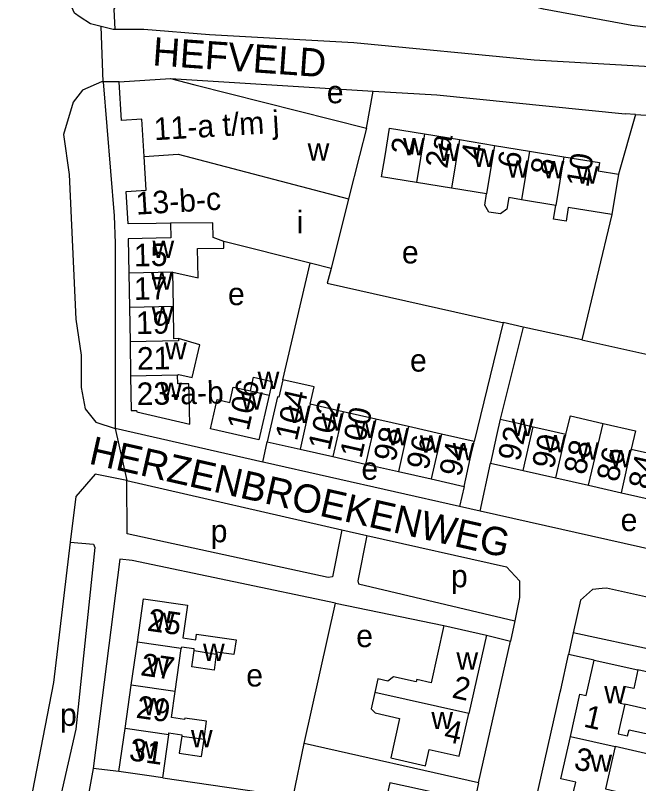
# Model space of a CAD drawing. Extents: x 163012 to 165277, y 382513 to 383987.
# Drawn here: x 163848.8 to 163959.5, y 383566.9 to 383703.3 of the extents above; entities that cross this region are included whole.
import ezdxf

# ---------------------------------------------------------------- set-up
doc = ezdxf.new("R2010")
doc.units = 0
for name, color, linetype in [('BLT_Basislijn', 7, 'Continuous'), ('BLT_Bebouwing', 7, 'Continuous'), ('BLT_Centroide', 7, 'Continuous'), ('BLT_Huisnummer', 7, 'Continuous'), ('BLT_Huisnummer_ tussenligend', 7, 'Continuous'), ('BLT_Huisnummer_reeks', 7, 'Continuous'), ('BLT_Onderverdeling_panden', 7, 'Continuous'), ('BLT_Straatnaam', 7, 'Continuous'), ('BLT_Vlakafsluiter', 7, 'Continuous')]:
    doc.layers.add(name, color=color, linetype=linetype)

msp = doc.modelspace()

# ---------------------------------------------------------------- linework, layer by layer
at = {"layer": 'BLT_Basislijn'}
for p, q in [((163864.34, 383691.46), (163864.06, 383691.46)), ((163867.17, 383691.48), (163864.34, 383691.46)), ((163876.3, 383692.03), (163912.31, 383689.83)), ((163911.11, 383683.25), (163912.31, 383689.83)), ((163958.91, 383685.64), (163955.89, 383675.07)), ((163958.91, 383685.64), (163957.06, 383685.77)), ((163958.91, 383685.64), (164004.75, 383682.98)), ((163954.72, 383667.91), (163949.39, 383645.66)), ((163896.25, 383638.61), (163901.09, 383659.27)), ((163935.4, 383648.75), (163930.26, 383627.64)), ((163938.97, 383647.95), (163934.89, 383631.6)), ((163938.97, 383647.95), (163935.4, 383648.75)), ((163949.39, 383645.66), (163938.97, 383647.95)), ((163949.39, 383645.66), (163990.87, 383636.39)), ((163892.68, 383624), (163866.5, 383629.96)), ((163892.68, 383624), (163893.49, 383627.6)), ((163931.33, 383615.29), (163933.13, 383623.81)), ((163868.54, 383620.71), (163906.76, 383611.96)), ((163928.46, 383619.68), (163927.66, 383616.12)), ((163931.33, 383615.29), (163927.66, 383616.12)), ((163983.4, 383603.59), (163931.33, 383615.29)), ((163906.76, 383611.96), (163911.21, 383610.95)), ((163900.04, 383574.07), (163905.62, 383598.92)), ((163905.62, 383598.92), (163924.87, 383594.99)), ((163937.48, 383595.84), (163936.71, 383592.2)), ((163932.43, 383593.29), (163936.71, 383592.2)), ((163947.84, 383593.68), (163946.99, 383589.85)), ((163975.18, 383587.76), (163947.84, 383593.68)), ((163931.03, 383567.07), (163936.71, 383592.2)), ((163945.61, 383583.59), (163946.99, 383589.85)), ((163951.54, 383588.86), (163946.99, 383589.85)), ((163976.48, 383583.2), (163959.34, 383587.1)), ((163976.54, 383576.59), (163956.98, 383581)), ((163898.07, 383564.6), (163900.04, 383574.07)), ((163931.03, 383567.07), (163900.04, 383574.07)), ((163867.16, 383569.05), (163862.59, 383569.6)), ((163874.93, 383567.94), (163898.07, 383564.6)), ((163931.03, 383567.07), (163907.55, 383460.42))]:
    msp.add_line(p, q, dxfattribs=at)
for points in [[(164049.11, 383697.12), (164020.26, 383697.6), (163986.78, 383698.92), (163970.65, 383700), (163958.23, 383701.46), (163942.55, 383704.38), (163930.77, 383707.49), (163916.3, 383712.29), (163898.28, 383719.17), (163879.5, 383726.81), (163866.23, 383704.35), (163866.45, 383700.78)], [(163860.29, 383702.92), (163859.23, 383703.63), (163858.28, 383705.77), (163857.55, 383709.28)], [(163864.02, 383701.27), (163862.08, 383701.73), (163860.29, 383702.92)], [(163866.45, 383700.78), (163866.12, 383700.78), (163864.02, 383701.27)], [(163964.63, 383693.94), (163940.93, 383695.32), (163908.87, 383698.4), (163883.22, 383699.83), (163871.58, 383700.78), (163866.45, 383700.78)], [(163864.06, 383691.46), (163860.66, 383689.97), (163859, 383687.84), (163857.33, 383682.14), (163858.28, 383675.01), (163859.47, 383649.36), (163860.42, 383642.95), (163860.42, 383637.25), (163861.13, 383633.45), (163863.03, 383631.08), (163866.5, 383629.96)], [(163864.34, 383691.46), (163866.32, 383667.71), (163866.46, 383662.83), (163866.5, 383629.96)], [(163912.31, 383689.83), (163923.59, 383689.14), (163957.06, 383685.77)], [(163904.83, 383658.33), (163904.14, 383655.71), (163935.01, 383648.84), (163935.4, 383648.75)], [(163927.66, 383616.12), (163892.98, 383623.93), (163892.68, 383624)], [(163868.54, 383620.71), (163862.9, 383621.83), (163859.49, 383617.87), (163858.48, 383609.78)], [(163906.76, 383611.96), (163905.06, 383603.63), (163904.34, 383603.52), (163868.64, 383611.23), (163868.54, 383620.71)], [(163911.21, 383610.95), (163909.57, 383602.93), (163909.73, 383602.38), (163937.48, 383595.84)], [(163911.21, 383610.95), (163936.01, 383605.38), (163938.31, 383602.89), (163938.27, 383599.94), (163937.48, 383595.84)], [(163858.48, 383609.78), (163862.64, 383609.43), (163862.86, 383608.82), (163859.49, 383576.6), (163853.78, 383551.38), (163852.82, 383551.19), (163849.14, 383551.93)], [(163858.48, 383609.78), (163855.5, 383584.89), (163849.14, 383551.93)], [(163905.62, 383598.92), (163869.51, 383606.52), (163867.33, 383606.74), (163862.59, 383569.6)], [(163977.2, 383596.4), (163953.73, 383601.62), (163952.97, 383601.58), (163951.27, 383601.38), (163949.15, 383599.47), (163947.84, 383593.68)], [(163941.12, 383563.72), (163945.51, 383583.15), (163945.61, 383583.59)], [(163862.59, 383569.6), (163859.01, 383550.05), (163841.02, 383473.95)]]:
    msp.add_lwpolyline(points, dxfattribs=at)
at = {"layer": 'BLT_Bebouwing'}
for p, q in [((163867.17, 383691.48), (163876.3, 383692.03)), ((163921.44, 383682.23), (163927.65, 383681.21)), ((163927.65, 383681.21), (163933.86, 383680.19)), ((163933.86, 383680.19), (163940.08, 383679.18)), ((163940.08, 383679.18), (163946.17, 383678.18)), ((163955.89, 383675.07), (163954.72, 383667.91)), ((163926.24, 383672.57), (163920.02, 383673.59)), ((163932.45, 383671.56), (163926.24, 383672.57)), ((163944.76, 383669.54), (163938.66, 383670.54)), ((163904.83, 383658.33), (163901.09, 383659.27)), ((163868.89, 383657.52), (163869, 383651.43)), ((163876.82, 383651.57), (163876.71, 383657.67)), ((163869, 383651.43), (163869.12, 383645.33)), ((163869.12, 383645.33), (163869.23, 383639.24)), ((163906.95, 383632.92), (163901.12, 383634.24)), ((163912.78, 383631.6), (163906.95, 383632.92)), ((163918.6, 383630.28), (163912.78, 383631.6)), ((163924.43, 383628.96), (163918.6, 383630.28)), ((163930.26, 383627.64), (163924.43, 383628.96)), ((163893.49, 383627.6), (163899.32, 383626.28)), ((163899.32, 383626.28), (163905.15, 383624.96)), ((163905.15, 383624.96), (163910.97, 383623.64)), ((163910.97, 383623.64), (163916.8, 383622.32)), ((163933.13, 383623.81), (163938.95, 383622.49)), ((163916.8, 383622.32), (163922.63, 383621)), ((163938.95, 383622.49), (163944.76, 383621.18)), ((163922.63, 383621), (163928.46, 383619.68)), ((163944.76, 383621.18), (163950.58, 383619.86)), ((163950.58, 383619.86), (163956.39, 383618.55)), ((163956.39, 383618.55), (163962.21, 383617.23)), ((163924.87, 383594.99), (163932.43, 383593.29)), ((163932.43, 383593.29), (163929.3, 383579.34)), ((163869.35, 383584.38), (163870.44, 383592.04)), ((163877.12, 383583.27), (163878.21, 383590.93)), ((163868.25, 383576.72), (163869.35, 383584.38)), ((163947.35, 383575.29), (163949.04, 383582.79)), ((163867.16, 383569.05), (163868.25, 383576.72)), ((163874.93, 383567.94), (163876.02, 383575.61))]:
    msp.add_line(p, q, dxfattribs=at)
for points in [[(163871.63, 383678.24), (163871.24, 383684.82), (163867.58, 383684.6), (163867.17, 383691.48)], [(163876.3, 383692.03), (163880.64, 383690.93), (163911.11, 383683.25)], [(163911.11, 383683.25), (163909.89, 383678.4), (163907.95, 383670.73)], [(163920.02, 383673.59), (163913.81, 383674.61), (163914.42, 383678.31), (163915.23, 383683.24), (163921.44, 383682.23)], [(163876.3, 383666.36), (163873.78, 383666.33), (163868.78, 383666.29), (163868.44, 383672.03), (163871.99, 383672.25), (163871.63, 383678.24)], [(163946.17, 383678.18), (163952.5, 383677.14), (163952.26, 383675.66), (163955.89, 383675.07)], [(163938.66, 383670.54), (163936.4, 383670.91), (163936.06, 383668.84), (163934.91, 383668.01), (163932.84, 383668.35), (163932.13, 383669.58), (163932.45, 383671.56)], [(163907.95, 383670.73), (163904.83, 383658.33)], [(163954.72, 383667.91), (163946.96, 383669.18), (163946.57, 383666.75), (163944.36, 383667.11), (163944.76, 383669.54)], [(163876.3, 383666.36), (163876.35, 383663.76), (163873.78, 383663.71), (163868.78, 383663.62), (163868.89, 383657.52)], [(163876.71, 383657.67), (163881.21, 383656.68), (163881.11, 383661.88), (163885.78, 383661.97), (163885.76, 383663.14)], [(163901.09, 383659.27), (163885.76, 383663.14)], [(163877.71, 383645.89), (163876.92, 383645.87), (163876.82, 383651.57)], [(163877.57, 383639.39), (163877.78, 383639.54), (163880.13, 383638.99), (163881.49, 383644.82), (163877.71, 383645.89)], [(163869.23, 383639.24), (163869.34, 383633.14), (163870.29, 383633.16), (163870.3, 383632.91), (163879.72, 383630.69), (163879.63, 383635.69), (163879.59, 383637.89), (163877.6, 383637.85), (163877.57, 383639.39)], [(163890.5, 383636.6), (163891.05, 383639.05), (163894.37, 383638.3), (163893.81, 383635.85)], [(163896.25, 383638.61), (163895.54, 383635.5), (163895.32, 383635.55), (163894.59, 383632.48), (163893.49, 383627.6)], [(163901.12, 383634.24), (163901.83, 383637.34), (163896.25, 383638.61)], [(163893.81, 383635.85), (163892.02, 383627.94), (163883.41, 383629.89), (163884.6, 383635.07), (163886.83, 383634.56), (163887.44, 383637.3), (163890.5, 383636.6)], [(163934.89, 383631.6), (163934.23, 383628.69), (163933.13, 383623.81)], [(163934.89, 383631.6), (163938.6, 383630.76), (163940.7, 383630.26)], [(163946.52, 383628.94), (163947.36, 383632.17), (163953.13, 383630.86)], [(163940.7, 383630.26), (163943.14, 383629.7), (163946.52, 383628.94)], [(163953.13, 383630.86), (163958.9, 383629.56), (163958.15, 383626.3)], [(163928.46, 383619.68), (163929.56, 383624.56), (163930.26, 383627.64)], [(163958.15, 383626.3), (163961.05, 383625.62), (163963.96, 383624.96)], [(163870.44, 383592.04), (163871.54, 383599.71), (163879.31, 383598.6), (163878.49, 383592.77), (163880.79, 383592.44), (163880.93, 383593.45), (163887.96, 383592.44), (163887.58, 383589.82), (163884.5, 383590.26), (163884.44, 383589.87)], [(163924.87, 383594.99), (163922.59, 383584.84), (163920.06, 383585.41), (163919.96, 383584.99), (163915.93, 383585.9), (163914.93, 383585.11), (163913.15, 383585.51), (163912.61, 383583.09)], [(163880.49, 383590.52), (163880.53, 383590.82), (163878.24, 383591.15), (163878.21, 383590.93)], [(163884.44, 383589.87), (163884.04, 383587.07), (163880.07, 383587.64), (163880.49, 383590.52)], [(163949.04, 383582.79), (163950.11, 383582.55), (163951.54, 383588.86)], [(163951.54, 383588.86), (163959.34, 383587.1)], [(163959.34, 383587.1), (163958.59, 383583.79), (163956.84, 383584.18), (163956.16, 383581.19), (163956.98, 383581)], [(163882.26, 383574.81), (163882.71, 383578.01), (163878.84, 383578.57), (163878.8, 383578.3), (163876.46, 383578.67), (163877.12, 383583.27)], [(163912.61, 383583.09), (163911.95, 383580.17), (163912.64, 383579.46), (163917, 383578.48), (163915.43, 383571.5), (163921.61, 383570.11), (163922.26, 383573.01), (163927.61, 383571.81), (163929.3, 383579.34)], [(163956.98, 383581), (163955.88, 383576.13), (163955.8, 383575.79), (163957.5, 383575.41), (163957.75, 383576.5), (163963.74, 383575.15), (163962.97, 383571.76), (163955.28, 383573.5)], [(163876.02, 383575.61), (163876.02, 383575.91), (163878.33, 383575.57), (163878.3, 383575.37)], [(163878.3, 383575.37), (163877.87, 383572.31), (163881.82, 383571.75), (163882.26, 383574.81)], [(163955.28, 383573.5), (163953.59, 383565.99), (163956.14, 383565.42), (163955.48, 383562.49), (163947.62, 383564.27), (163948.29, 383567.19), (163945.65, 383567.79), (163947.35, 383575.29)], [(163874.93, 383567.94), (163872.11, 383568.35), (163867.16, 383569.05)], [(163921.45, 383557.78), (163923.15, 383565.33), (163918.27, 383566.43), (163915.29, 383567.09), (163913.57, 383559.55)]]:
    msp.add_lwpolyline(points, dxfattribs=at)
at = {"layer": 'BLT_Onderverdeling_panden'}
for p, q in [((163921.44, 383682.23), (163920.02, 383673.59)), ((163927.65, 383681.21), (163926.24, 383672.57)), ((163933.86, 383680.19), (163932.45, 383671.56)), ((163940.08, 383679.18), (163938.66, 383670.54)), ((163946.17, 383678.18), (163944.76, 383669.54)), ((163876.71, 383657.67), (163868.89, 383657.52)), ((163876.82, 383651.57), (163869, 383651.43)), ((163877.57, 383639.39), (163869.23, 383639.24)), ((163890.5, 383636.6), (163893.81, 383635.85)), ((163901.12, 383634.24), (163899.32, 383626.28)), ((163906.95, 383632.92), (163905.15, 383624.96)), ((163912.78, 383631.6), (163910.97, 383623.64)), ((163918.6, 383630.28), (163916.8, 383622.32)), ((163938.95, 383622.49), (163940.7, 383630.26)), ((163950.58, 383619.86), (163953.13, 383630.86)), ((163924.43, 383628.96), (163922.63, 383621)), ((163944.76, 383621.18), (163946.52, 383628.94)), ((163956.39, 383618.55), (163958.15, 383626.3)), ((163878.21, 383590.93), (163870.44, 383592.04)), ((163880.49, 383590.52), (163884.44, 383589.87)), ((163877.12, 383583.27), (163869.35, 383584.38)), ((163929.3, 383579.34), (163912.61, 383583.09)), ((163876.02, 383575.61), (163868.25, 383576.72)), ((163878.3, 383575.37), (163882.26, 383574.81)), ((163947.35, 383575.29), (163955.28, 383573.5))]:
    msp.add_line(p, q, dxfattribs=at)
for points in [[(163871.63, 383678.24), (163877.68, 383678.6), (163907.95, 383670.73)], [(163885.76, 383663.14), (163883.86, 383663.83), (163883.84, 383666.42), (163876.3, 383666.36)], [(163877.71, 383645.89), (163877.72, 383645.49), (163869.12, 383645.33)]]:
    msp.add_lwpolyline(points, dxfattribs=at)
at = {"layer": 'BLT_Vlakafsluiter'}
for p, q in [((163864.34, 383691.46), (163864.02, 383701.27)), ((163866.5, 383629.96), (163868.54, 383620.71))]:
    msp.add_line(p, q, dxfattribs=at)

# ---------------------------------------------------------------- texts
at = {"layer": 'BLT_Centroide'}
for s, p in [('e', (163904.07, 383687.66)), ('w', (163900.66, 383677.49)), ('w', (163917.62, 383678.41)), ('w', (163923.84, 383677.41)), ('w', (163930.05, 383676.38)), ('w', (163936.09, 383674.45)), ('w', (163942.42, 383674.36)), ('w', (163948.44, 383673.38)), ('i', (163898.73, 383664.58)), ('w', (163873.1, 383660.22)), ('e', (163917.41, 383659.24)), ('w', (163872.85, 383654.56)), ('e', (163886.52, 383651.84)), ('w', (163872.97, 383648.47)), ('w', (163875.34, 383642.19)), ('e', (163918.85, 383640.04)), ('w', (163891.78, 383636.93)), ('w', (163874.48, 383635.03)), ('w', (163888.83, 383633.31)), ('w', (163897.31, 383630.92)), ('w', (163903.14, 383629.59)), ('w', (163908.97, 383628.28)), ('w', (163936.92, 383628.59)), ('w', (163914.78, 383626.97)), ('w', (163920.61, 383625.64)), ('w', (163942.73, 383625.7)), ('w', (163926.44, 383624.31)), ('w', (163948.55, 383624.39)), ('w', (163954.36, 383623.08)), ('e', (163910.22, 383620.85)), ('e', (163956.26, 383611.73)), ('p', (163883.45, 383609.76)), ('p', (163926.12, 383601.77)), ('w', (163873.17, 383594.18)), ('e', (163909.29, 383591.15)), ('w', (163882.08, 383588.7)), ('w', (163872.21, 383586.19)), ('w', (163927.09, 383587.16)), ('e', (163889.76, 383584.16)), ('w', (163953.34, 383581.2)), ('w', (163871.43, 383579.06)), ('p', (163856.69, 383577.17)), ('w', (163922.63, 383576.59)), ('w', (163879.93, 383573.39)), ('w', (163869.92, 383571.38)), ('w', (163950.89, 383569.02))]:
    msp.add_text(s, height=4, dxfattribs=at).set_placement(p)
at = {"layer": 'BLT_Huisnummer'}
for s, rotation, p in [('2a', 80.7013, (163925.46, 383675.96)), ('2', 80.7023, (163919.34, 383678.29)), ('4', 80.7023, (163931.81, 383677.3)), ('10', 80.7059, (163950.51, 383672.59)), ('15', 1.0619, (163869.85, 383658.7)), ('21', 1.0591, (163870.38, 383640.36)), ('106', 77.2443, (163890.17, 383629.39)), ('104', 77.2443, (163898.74, 383627.59)), ('98', 77.2427, (163916.21, 383623.88)), ('92', 77.2448, (163938.29, 383623.95)), ('94', 77.245, (163927.86, 383621.22)), ('88', 77.2414, (163949.98, 383621.57)), ('84', 77.2438, (163961.45, 383618.93)), ('25', 351.8689, (163872.03, 383594.09)), ('2', 347.3349, (163926.14, 383582.24)), ('1', 347.2787, (163949.53, 383577.07)), ('4', 347.3394, (163924.69, 383574.51)), ('31', 351.8715, (163868.81, 383571.09)), ('3', 347.2811, (163947.78, 383569.55))]:
    msp.add_text(s, height=4, rotation=rotation, dxfattribs=at).set_placement(p)
at = {"layer": 'BLT_Huisnummer_ tussenligend'}
for s, rotation, p in [('6', 80.7023, (163938.32, 383675.93)), ('8', 80.7023, (163944.14, 383674.74)), ('17', 1.0619, (163869.84, 383652.76)), ('19', 1.0591, (163870.21, 383646.69)), ('102', 77.2427, (163904.58, 383625.89)), ('100', 77.2427, (163910.22, 383624.5)), ('96', 77.245, (163922.04, 383622.42)), ('90', 77.2414, (163944.33, 383622.59)), ('86', 77.2438, (163955.8, 383620.3)), ('27', 351.8689, (163870.83, 383586.17)), ('29', 351.8689, (163870.05, 383578.64))]:
    msp.add_text(s, height=4, rotation=rotation, dxfattribs=at).set_placement(p)
at = {"layer": 'BLT_Huisnummer_reeks'}
for s, rotation, p in [('11-a t/m j', 3.4446, (163873.47, 383681.09)), ('13-b-c', 3.4439, (163870.24, 383667.88)), ('23-a-b', 1.0649, (163870.34, 383634.09))]:
    msp.add_text(s, height=4, rotation=rotation, dxfattribs=at).set_placement(p)
at = {"layer": 'BLT_Straatnaam'}
for s, rotation, p in [('HEFVELD', 356.0002, (163873.02, 383694.41)), ('HERZENBROEKENWEG', 347.293, (163861.63, 383623.74))]:
    msp.add_text(s, height=5, rotation=rotation, dxfattribs=at).set_placement(p)

doc.saveas('drawing.dxf')
